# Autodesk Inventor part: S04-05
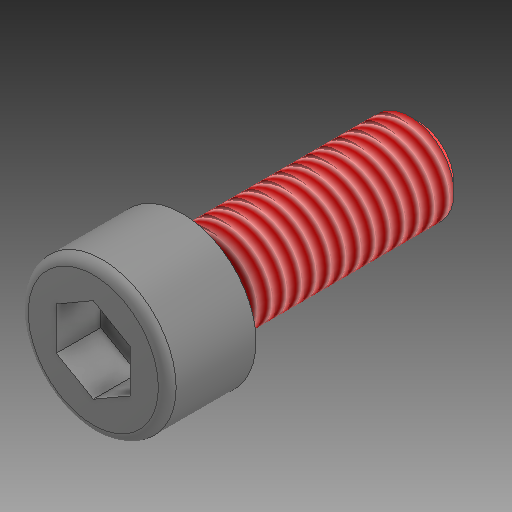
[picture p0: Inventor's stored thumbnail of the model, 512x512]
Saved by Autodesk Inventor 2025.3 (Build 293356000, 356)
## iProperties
Manager: ISO 4762 (DIN 912)
Created: 2025-05
Part Number: S04-05
Material: Všeobecné
Description: Imbusový šroub s válcovou hlavou
Document SubType Name: Modeling
Designer: Patrik
Stock Number: E 1200/6x16
Mass: 0.853299 g
Surface Area: 6.8161 cm^2
Volume: 0.853299 cm^3
Density: 1 g/cm^3
Appearance: Výchozí
User Status: 12.9
Sending System: KiM GmbH
Major Version: 4.0
Minor Version: 0.0
Format Version: 0.0
Product Id: KiM GmbH
cc_prop_force_one_body: 1
Hersteller: Meusburger
Material: 12.9 ISO 4762 (DIN 912)
Bestellnummer: E 1200/6x16
Teilenummer: E 1200/6x16
Beschreibung: Zylinderkopfschraube mit Innensechskant _ Cylinder head screw with hexagon socket
Author: Patrik
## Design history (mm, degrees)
derived "E 1200_6x16.ipt"
feature "Těleso1::E 1200_6x16.ipt" dims "d0" = 10
tag "Prvek štítků1"
node "Těleso1"
